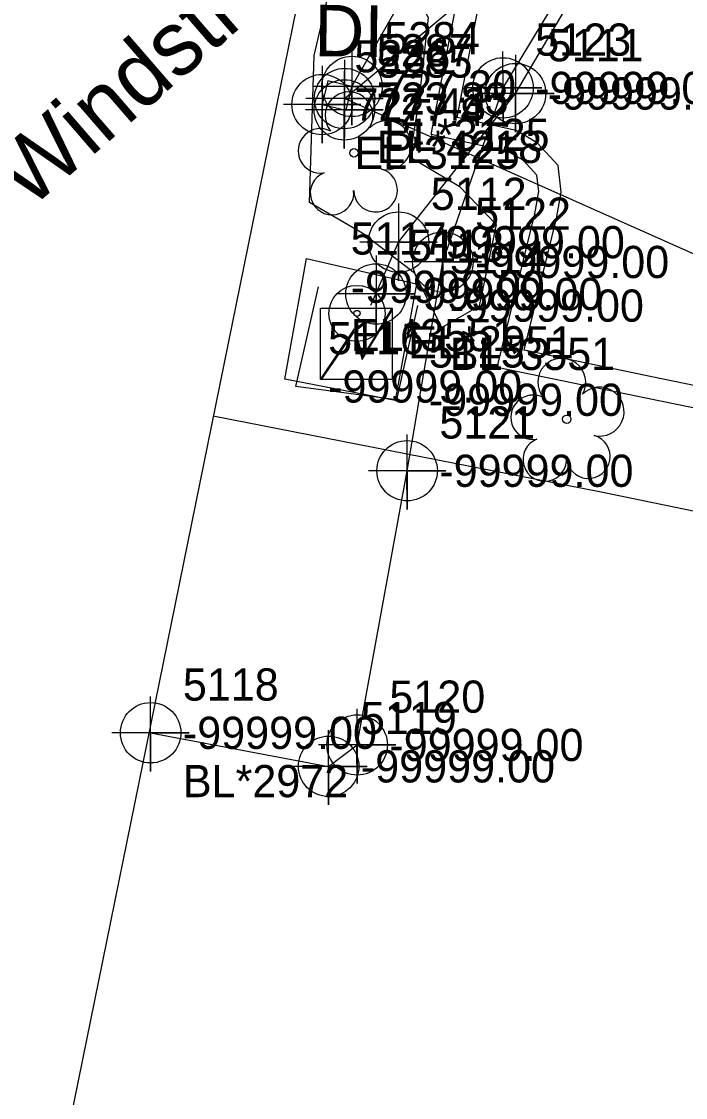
# Model space of a CAD drawing. Extents: x 1516784 to 1522736, y 634838 to 639369.
# Drawn here: x 1520757 to 1520808.5, y 638601 to 638684.5 of the extents above; entities that cross this region are included whole.
import ezdxf

# ---------------------------------------------------------------- set-up
doc = ezdxf.new("R2010")
doc.units = 0
for name, color, linetype in [('Exist Building', 7, 'Continuous'), ('Exist Environmental Wetland Boundary Cogo Number', 7, 'Continuous'), ('Exist Environmental Wetland Boundary Cogo Point CELL', 7, 'Continuous'), ('Exist Other Culture Area Outline', 7, 'Continuous'), ('Exist Other Culture Located Object CELL', 7, 'Continuous'), ('Exist Structure Minor Drop Inlet', 7, 'Continuous'), ('Exist Structure Minor Drop Inlet Cogo Comment', 7, 'Continuous'), ('Exist Structure Minor Drop Inlet Cogo Elevation', 7, 'Continuous'), ('Exist Structure Minor Drop Inlet Cogo Number', 7, 'Continuous'), ('Exist Structure Minor Drop Inlet Cogo Point CELL', 7, 'Continuous'), ('Exist Structure Minor Drop Inlet Leader', 7, 'Continuous'), ('Exist Structure Minor Drop Inlet Text', 7, 'Continuous'), ('Exist Structure Minor Pipes RCP 18 Inch', 7, 'Continuous'), ('Exist Structure Minor Pipes RCP 18 Inch Cogo Comment', 7, 'Continuous'), ('Exist Structure Minor Pipes RCP 18 Inch Cogo Elevation', 7, 'Continuous'), ('Exist Structure Minor Pipes RCP 18 Inch Cogo Number', 7, 'Continuous'), ('Exist Structure Minor Pipes RCP 18 Inch Cogo Point CELL', 7, 'Continuous'), ('Exist Structure Minor Pipes RCP 18 Inch Leader', 7, 'Continuous'), ('Exist Utilities Power Transformer CELL', 7, 'Continuous'), ('Exist Utilities Power Transformer Cogo Comment', 7, 'Continuous'), ('Exist Utilities Power Transformer Cogo Elevation', 7, 'Continuous'), ('Exist Utilities Power Transformer Cogo Number', 7, 'Continuous'), ('Exist Utilities Power UG Cable SUE LOS B', 7, 'Continuous'), ('Exist Utilities Power UG Cable SUE LOS B Cogo Comment', 7, 'Continuous'), ('Exist Utilities Power UG Cable SUE LOS B Cogo Elevation', 7, 'Continuous'), ('Exist Utilities Power UG Cable SUE LOS B Cogo Number', 7, 'Continuous'), ('Exist Utilities Power UG Cable SUE LOS B Cogo Point CELL', 7, 'Continuous'), ('Exist Utilities Telephone UG Conduit SUE LOS B', 7, 'Continuous'), ('Exist Utilities Telephone UG Conduit SUE LOS B Cogo Comment', 7, 'Continuous'), ('Exist Utilities Telephone UG Conduit SUE LOS B Cogo Elevation', 7, 'Continuous'), ('Exist Utilities Telephone UG Conduit SUE LOS B Cogo Number', 7, 'Continuous'), ('Exist Utilities Telephone UG Conduit SUE LOS B Cogo Point CELL', 7, 'Continuous'), ('Exist Utilities Telephone UG Conduit SUE LOS B Text', 7, 'Continuous'), ('Exist Vegetation Hedge Row', 7, 'Continuous'), ('Exist Vegetation Tree CELL', 7, 'Continuous'), ('Old_Level_4', 7, 'Continuous')]:
    doc.layers.add(name, color=color, linetype=linetype)

msp = doc.modelspace()

# ---------------------------------------------------------------- linework, layer by layer
at = {"layer": 'Exist Building'}
msp.add_lwpolyline([(1520578.554, 638507.738), (1520628.438, 638753.096), (1520785.559, 638721.152), (1520735.676, 638475.794)], close=True, dxfattribs=at)
at = {"layer": 'Exist Environmental Wetland Boundary Cogo Number'}
for points in [[(1520833.181, 638649.572), (1520805.563, 638655.25), (1520793.915, 638657.67), (1520796.825, 638669.584), (1520797.146, 638671.316), (1520796.993, 638672.58), (1520795.918, 638673.743), (1520794.743, 638674.434), (1520788.795, 638675.758), (1520793.92, 638702.467)], [(1520771.886, 638653.9), (1520801.842, 638648.019), (1520841.838, 638639.783)]]:
    msp.add_lwpolyline(points, dxfattribs=at)
at = {"layer": 'Exist Environmental Wetland Boundary Cogo Point CELL'}
msp.add_lwpolyline([(1520849.952, 638647.564), (1520833.543, 638651.252), (1520805.911, 638656.932), (1520796.006, 638658.991), (1520798.505, 638669.223), (1520798.883, 638671.261), (1520798.632, 638673.338), (1520797.008, 638675.095), (1520795.38, 638676.052), (1520790.797, 638677.073), (1520795.277, 638700.419), (1520804.004, 638698.551), (1520807.231, 638715.037), (1520813.426, 638713.586), (1520814.853, 638713.262)], dxfattribs=at)
at = {"layer": 'Exist Other Culture Area Outline'}
msp.add_lwpolyline([(1520787.635, 638664.154), (1520785.994, 638655.091), (1520777.424, 638656.752), (1520779.103, 638666.108), (1520787.635, 638664.154)], dxfattribs=at)
at = {"layer": 'Exist Other Culture Located Object CELL'}
for radius in [2.18, 0.24]:
    msp.add_circle((1520783.026, 638661.856), radius, dxfattribs=at)
at = {"layer": 'Exist Structure Minor Drop Inlet'}
msp.add_lwpolyline([(1520780.328, 638678.071), (1520782.201, 638677.624), (1520782.643, 638679.477), (1520780.77, 638679.924)], close=True, dxfattribs=at)
at = {"layer": 'Exist Structure Minor Drop Inlet Cogo Point CELL'}
for points in [[(1520782.643, 638682.477), (1520782.643, 638676.477), (1520782.643, 638679.477), (1520785.643, 638679.477), (1520779.643, 638679.477)], [(1520780.328, 638681.071), (1520780.328, 638675.071), (1520780.328, 638678.071), (1520783.328, 638678.071), (1520777.328, 638678.071)], [(1520782.049, 638680.66), (1520782.049, 638674.66), (1520782.049, 638677.66), (1520785.049, 638677.66), (1520779.049, 638677.66)]]:
    msp.add_lwpolyline(points, dxfattribs=at)
for centre in [(1520782.643, 638679.477), (1520780.328, 638678.071), (1520782.049, 638677.66)]:
    msp.add_circle(centre, 2.344, dxfattribs=at)
at = {"layer": 'Exist Structure Minor Drop Inlet Leader'}
msp.add_lwpolyline([(1520782.643, 638679.477), (1520789.82, 638691.99), (1520795.82, 638691.99)], dxfattribs=at)
at = {"layer": 'Exist Structure Minor Pipes RCP 18 Inch'}
msp.add_line((1520860.213, 638643.683), (1520782.065, 638678.538), dxfattribs=at)
at = {"layer": 'Exist Structure Minor Pipes RCP 18 Inch Cogo Point CELL'}
msp.add_lwpolyline([(1520782.065, 638681.538), (1520782.065, 638675.538), (1520782.065, 638678.538), (1520785.065, 638678.538), (1520779.065, 638678.538)], dxfattribs=at)
msp.add_circle((1520782.065, 638678.538), 2.344, dxfattribs=at)
at = {"layer": 'Exist Structure Minor Pipes RCP 18 Inch Leader'}
msp.add_lwpolyline([(1520782.065, 638678.538), (1520791.705, 638686.623), (1520797.705, 638686.623)], dxfattribs=at)
at = {"layer": 'Exist Utilities Power Transformer CELL'}
msp.add_line((1520783.046, 638659.663), (1520783.046, 638659.663), dxfattribs=at)
msp.add_lwpolyline([(1520780.203, 638662.274), (1520785.755, 638662.274), (1520785.755, 638656.721), (1520780.203, 638656.721)], close=True, dxfattribs=at)
for points in [[(1520780.203, 638656.721), (1520782.846, 638660.665), (1520783.475, 638658.456), (1520785.755, 638662.274)], [(1520780.273, 638656.721), (1520782.846, 638660.456), (1520783.433, 638658.274), (1520785.755, 638662.12)]]:
    msp.add_lwpolyline(points, dxfattribs=at)
at = {"layer": 'Exist Utilities Power UG Cable SUE LOS B'}
msp.add_lwpolyline([(1520784.113, 638662.494), (1520786.254, 638667.391), (1520795.328, 638678.928), (1520804.538, 638694.542), (1520820.114, 638707.825), (1520836.889, 638721.363), (1520846.968, 638733.099), (1520857.28, 638746.046), (1520866.498, 638761.495), (1520885.977, 638785.26), (1520895.148, 638798.159), (1520899.425, 638804.825)], dxfattribs=at)
at = {"layer": 'Exist Utilities Power UG Cable SUE LOS B Cogo Point CELL'}
for points in [[(1520795.328, 638681.928), (1520795.328, 638675.928), (1520795.328, 638678.928), (1520798.328, 638678.928), (1520792.328, 638678.928)], [(1520786.254, 638670.391), (1520786.254, 638664.391), (1520786.254, 638667.391), (1520789.254, 638667.391), (1520783.254, 638667.391)], [(1520784.509, 638666.366), (1520784.509, 638660.366), (1520784.509, 638663.366), (1520787.509, 638663.366), (1520781.509, 638663.366)]]:
    msp.add_lwpolyline(points, dxfattribs=at)
for centre in [(1520795.328, 638678.928), (1520786.254, 638667.391), (1520784.509, 638663.366)]:
    msp.add_circle(centre, 2.344, dxfattribs=at)
at = {"layer": 'Exist Utilities Telephone UG Conduit SUE LOS B'}
msp.add_lwpolyline([(1520767.023, 638629.297), (1520780.833, 638626.694), (1520783.044, 638628.355), (1520786.921, 638649.642), (1520789.694, 638665.851), (1520794.358, 638679.365), (1520803.878, 638695.098), (1520819.519, 638708.633), (1520836.327, 638722.159), (1520846.505, 638733.886), (1520856.458, 638746.655), (1520865.818, 638761.863), (1520885.587, 638785.372), (1520894.619, 638798.674), (1520899.221, 638805.419)], dxfattribs=at)
at = {"layer": 'Exist Utilities Telephone UG Conduit SUE LOS B Cogo Point CELL'}
for points in [[(1520794.325, 638682.18), (1520794.358, 638676.365), (1520794.341, 638679.365), (1520797.358, 638679.365), (1520791.358, 638679.365)], [(1520789.661, 638668.666), (1520789.694, 638662.851), (1520789.677, 638665.851), (1520792.694, 638665.851), (1520786.694, 638665.851)], [(1520786.888, 638652.457), (1520786.921, 638646.642), (1520786.904, 638649.642), (1520789.921, 638649.642), (1520783.921, 638649.642)], [(1520766.99, 638632.111), (1520767.023, 638626.297), (1520767.006, 638629.297), (1520770.023, 638629.297), (1520764.023, 638629.297)], [(1520783.011, 638631.17), (1520783.044, 638625.355), (1520783.027, 638628.355), (1520786.044, 638628.355), (1520780.044, 638628.355)], [(1520780.801, 638629.509), (1520780.833, 638623.694), (1520780.816, 638626.694), (1520783.833, 638626.694), (1520777.833, 638626.694)]]:
    msp.add_lwpolyline(points, dxfattribs=at)
for centre in [(1520794.358, 638679.365), (1520789.694, 638665.851), (1520786.921, 638649.642), (1520767.023, 638629.297), (1520783.044, 638628.355), (1520780.833, 638626.694)]:
    msp.add_circle(centre, 2.344, dxfattribs=at)
at = {"layer": 'Exist Vegetation Hedge Row'}
msp.add_lwpolyline([(1520787.942, 638719.343), (1520790.992, 638716.264), (1520792.771, 638711.198), (1520792.108, 638703.243), (1520790.13, 638693.142), (1520787.85, 638692.32), (1520786.471, 638688.894), (1520788.542, 638684.838), (1520787.867, 638678.593), (1520787.124, 638674.011), (1520790.964, 638671.74), (1520793.826, 638668.763), (1520792.497, 638662.421), (1520789.609, 638660.776), (1520787.495, 638664.992), (1520783.494, 638668.07), (1520779.341, 638670.47), (1520779.716, 638681.891), (1520783.63, 638698.618), (1520787.942, 638719.343)], dxfattribs=at)
at = {"layer": 'Exist Vegetation Tree CELL'}
for p, q in [((1520782.798, 638674.325), (1520782.798, 638674.325)), ((1520799.301, 638653.642), (1520799.301, 638653.642))]:
    msp.add_line(p, q, dxfattribs=at)
for centre in [(1520782.798, 638674.325), (1520799.301, 638653.642)]:
    msp.add_circle(centre, 0.326, dxfattribs=at)
for centre, radius, start, end in [((1520782.413, 638677.198), 1.856, 330.16508, 219.71335), ((1520780.193, 638674.479), 1.727, 62.66361, 279.3457), ((1520785.347, 638674.914), 1.899, 257.1011, 134.19993), ((1520781.094, 638671.204), 1.689, 111.56708, 6.23104), ((1520784.471, 638671.426), 1.698, 181.28216, 74.55999), ((1520798.916, 638656.515), 1.856, 330.16508, 219.71335), ((1520801.85, 638654.23), 1.899, 257.1011, 134.19993), ((1520796.695, 638653.795), 1.727, 62.66361, 279.3457), ((1520797.597, 638650.521), 1.689, 111.56708, 6.23104), ((1520800.974, 638650.742), 1.698, 181.28216, 74.55999)]:
    msp.add_arc(centre, radius, start, end, dxfattribs=at)
at = {"layer": 'Old_Level_4'}
msp.add_lwpolyline([(1520787.731, 638662.463), (1520786.108, 638655.153), (1520778.289, 638656.184), (1520780.041, 638663.927)], dxfattribs=at)

# ---------------------------------------------------------------- texts
at = {"layer": 'Exist Structure Minor Drop Inlet Cogo Comment'}
for s, p in [('BL*3125', (1520785.143, 638674.477)), ('EL*3125', (1520782.828, 638673.071))]:
    msp.add_text(s, height=2.5, dxfattribs=at).set_placement(p)
at = {"layer": 'Exist Structure Minor Drop Inlet Cogo Elevation'}
for s, p in [('727.30', (1520785.143, 638678.227)), ('727.43', (1520782.828, 638676.821)), ('727.42', (1520784.549, 638676.41))]:
    msp.add_text(s, height=2.5, dxfattribs=at).set_placement(p)
at = {"layer": 'Exist Structure Minor Drop Inlet Cogo Number'}
for s, p in [('5284', (1520785.143, 638681.977)), ('5286', (1520782.828, 638680.571)), ('5285', (1520784.549, 638680.16))]:
    msp.add_text(s, height=2.5, dxfattribs=at).set_placement(p)
at = {"layer": 'Exist Structure Minor Drop Inlet Text'}
msp.add_text('DI', height=4, rotation=359.30231, dxfattribs=at).set_placement((1520779.706, 638681.826))
at = {"layer": 'Exist Structure Minor Pipes RCP 18 Inch Cogo Comment'}
msp.add_text('EL*4218', height=2.5, dxfattribs=at).set_placement((1520784.565, 638673.538))
at = {"layer": 'Exist Structure Minor Pipes RCP 18 Inch Cogo Elevation'}
msp.add_text('723.83', height=2.5, dxfattribs=at).set_placement((1520784.565, 638677.288))
at = {"layer": 'Exist Structure Minor Pipes RCP 18 Inch Cogo Number'}
msp.add_text('5287', height=2.5, dxfattribs=at).set_placement((1520784.565, 638681.038))
at = {"layer": 'Exist Utilities Power Transformer Cogo Comment'}
for s, p in [('EL*3551', (1520782.541, 638658.927)), ('BL*3551', (1520790.231, 638657.463))]:
    msp.add_text(s, height=2.5, dxfattribs=at).set_placement(p)
at = {"layer": 'Exist Utilities Power Transformer Cogo Elevation'}
for p in [(1520782.541, 638662.677), (1520790.231, 638661.213), (1520780.789, 638654.934), (1520788.608, 638653.903)]:
    msp.add_text('-99999.00', height=2.5, dxfattribs=at).set_placement(p)
at = {"layer": 'Exist Utilities Power Transformer Cogo Number'}
for s, p in [('5117', (1520782.541, 638666.427)), ('5114', (1520790.231, 638664.963)), ('5116', (1520780.789, 638658.684)), ('5115', (1520788.608, 638657.653))]:
    msp.add_text(s, height=2.5, dxfattribs=at).set_placement(p)
at = {"layer": 'Exist Utilities Power UG Cable SUE LOS B Cogo Comment'}
msp.add_text('EL*2951', height=2.5, dxfattribs=at).set_placement((1520787.009, 638658.366))
at = {"layer": 'Exist Utilities Power UG Cable SUE LOS B Cogo Elevation'}
for p in [(1520797.828, 638677.678), (1520788.754, 638666.141), (1520787.009, 638662.116)]:
    msp.add_text('-99999.00', height=2.5, dxfattribs=at).set_placement(p)
at = {"layer": 'Exist Utilities Power UG Cable SUE LOS B Cogo Number'}
for s, p in [('5111', (1520797.828, 638681.428)), ('5112', (1520788.754, 638669.891)), ('5113', (1520787.009, 638665.866))]:
    msp.add_text(s, height=2.5, dxfattribs=at).set_placement(p)
at = {"layer": 'Exist Utilities Telephone UG Conduit SUE LOS B Cogo Comment'}
msp.add_text('BL*2972', height=2.5, dxfattribs=at).set_placement((1520769.523, 638624.297))
at = {"layer": 'Exist Utilities Telephone UG Conduit SUE LOS B Cogo Elevation'}
for p in [(1520796.858, 638678.115), (1520792.194, 638664.601), (1520789.421, 638648.392), (1520769.523, 638628.047), (1520785.544, 638627.105), (1520783.333, 638625.444)]:
    msp.add_text('-99999.00', height=2.5, dxfattribs=at).set_placement(p)
at = {"layer": 'Exist Utilities Telephone UG Conduit SUE LOS B Cogo Number'}
for s, p in [('5123', (1520796.858, 638681.865)), ('5122', (1520792.194, 638668.351)), ('5121', (1520789.421, 638652.142)), ('5118', (1520769.523, 638631.797)), ('5120', (1520785.544, 638630.855)), ('5119', (1520783.333, 638629.194))]:
    msp.add_text(s, height=2.5, dxfattribs=at).set_placement(p)
at = {"layer": 'Exist Utilities Telephone UG Conduit SUE LOS B Text'}
msp.add_text('Windstream Communications Inc.,', height=5, rotation=40.87101, dxfattribs=at).set_placement((1520757.582, 638669.827))

doc.saveas('drawing.dxf')
